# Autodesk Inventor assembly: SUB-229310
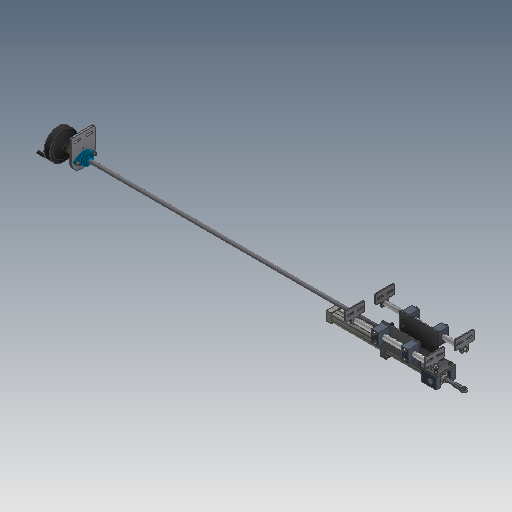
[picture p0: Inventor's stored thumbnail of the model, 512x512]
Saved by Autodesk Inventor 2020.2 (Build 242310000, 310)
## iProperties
Created: 2000-02
Part Number: SUB-229310
Document SubType Name: Assembly
Designer: sspink
Mass: 18139.2 g
Surface Area: 10168 cm^2
Volume: 3700.38 cm^3
Density: 4.90199 g/cm^3
Control State: 0
Checked Out: False
Master: False
Shininess: 0.0
Length Units: 11269
Angle Units: 11279
Time Units: 11290
Mass Units: 11283
Length Display Precision: 3
Angle Display Precision: 2
Compacted: True
Dimensions: 226,3x2253,1x261 mm
Mass: 18,139 kg
DocNumber: SUB-229310.iam
Folder: 01 - Themengebiete\Simplification\01 - Packaging machine\
VDS_Category: 3D Komponenten
Density: 0.0
Volumn: 0.0
Area: 0.0
PropertySet Name: Model Information
Author: sspink
Revision Number: -
Title: SUB-229310
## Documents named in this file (25)
- D:\07 - DEMODATEN\OTX 2019 - Dataset - UPDATE - Dez2019\Designs\07-Packing machine\SUB-229310.iam
- D:\07 - DEMODATEN\OTX 2019 - Dataset - UPDATE - Dez2019\Designs\07-Packing machine\Parts\ADSK-011610.ipt
- D:\07 - DEMODATEN\OTX 2019 - Dataset - UPDATE - Dez2019\Designs\07-Packing machine\Parts\ADSK-011611.ipt
- D:\07 - DEMODATEN\OTX 2019 - Dataset - UPDATE - Dez2019\Designs\07-Packing machine\Parts\ADSK-011577.ipt
- D:\07 - DEMODATEN\OTX 2019 - Dataset - UPDATE - Dez2019\Designs\07-Packing machine\Parts\ADSK-011333.ipt
- D:\07 - DEMODATEN\OTX 2019 - Dataset - UPDATE - Dez2019\Designs\07-Packing machine\Parts\ADSK-011576.ipt
- D:\07 - DEMODATEN\OTX 2019 - Dataset - UPDATE - Dez2019\Designs\07-Packing machine\500616.iam
- D:\07 - DEMODATEN\OTX 2019 - Dataset - UPDATE - Dez2019\Designs\07-Packing machine\500615.iam
- D:\07 - DEMODATEN\OTX 2019 - Dataset - UPDATE - Dez2019\Designs\07-Packing machine\A105157.iam
- D:\07 - DEMODATEN\OTX 2019 - Dataset - UPDATE - Dez2019\Designs\07-Packing machine\A081742.iam
- D:\07 - DEMODATEN\OTX 2019 - Dataset - UPDATE - Dez2019\Designs\07-Packing machine\Parts\ADSK-011614.ipt
- D:\07 - DEMODATEN\OTX 2019 - Dataset - UPDATE - Dez2019\Designs\07-Packing machine\Parts\ADSK-011714.ipt
- D:\07 - DEMODATEN\OTX 2019 - Dataset - UPDATE - Dez2019\Designs\07-Packing machine\Parts\ADSK-011309.ipt
- D:\07 - DEMODATEN\OTX 2019 - Dataset - UPDATE - Dez2019\Designs\07-Packing machine\Parts\ADSK-011768.ipt
- D:\07 - DEMODATEN\OTX 2019 - Dataset - UPDATE - Dez2019\Designs\07-Packing machine\Parts\ADSK-011615.ipt
- D:\07 - DEMODATEN\OTX 2019 - Dataset - UPDATE - Dez2019\Designs\07-Packing machine\Parts\ADSK-011725.ipt
- D:\07 - DEMODATEN\OTX 2019 - Dataset - UPDATE - Dez2019\Content Center Files\de-DE\DIN 125-1  B\DIN 125-1 - B 13.ipt
- D:\07 - DEMODATEN\OTX 2019 - Dataset - UPDATE - Dez2019\Content Center Files\de-DE\ISO 4762(2)\ISO 4762 - M12 x 25ISO.ipt
- D:\07 - DEMODATEN\OTX 2019 - Dataset - UPDATE - Dez2019\Content Center Files\de-DE\DIN 125-1  B\DIN 125-1 - B 8,4.ipt
- D:\07 - DEMODATEN\OTX 2019 - Dataset - UPDATE - Dez2019\Content Center Files\de-DE\ISO 4032(1)\ISO 4032 - M8DIN EN.ipt
- D:\07 - DEMODATEN\OTX 2019 - Dataset - UPDATE - Dez2019\Content Center Files\de-DE\ISO 4762(2)\ISO 4762 - M8 x 80ISO.ipt
- D:\07 - DEMODATEN\OTX 2019 - Dataset - UPDATE - Dez2019\Content Center Files\de-DE\ISO 4762(2)\ISO 4762 - M8 x 16ISO.ipt
- D:\07 - DEMODATEN\OTX 2019 - Dataset - UPDATE - Dez2019\Content Center Files\de-DE\ISO 4762(2)\ISO 4762 - M8 x 25ISO.ipt
- D:\07 - DEMODATEN\OTX 2019 - Dataset - UPDATE - Dez2019\Content Center Files\de-DE\DIN 125-1  B\DIN 125-1 - B 5,3.ipt
- D:\07 - DEMODATEN\OTX 2019 - Dataset - UPDATE - Dez2019\Content Center Files\de-DE\ISO 4762(2)\ISO 4762 - M5 x 8ISO.ipt
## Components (82 placed, 24 different names)
1. ADSK-011610:1 — Flush:1, Flush:2, Insert:1, Flush:3, Mate:1, Mate:2, Angle:2, Flush:7, Flush:8, Mate:16
2. ADSK-011610:2 — Flush:1, Flush:2, Insert:2, Angle:3, Flush:9, Flush:10
3. ADSK-011610:3 — Flush:7, Flush:8, Insert:10, Fluchtend:14
4. ADSK-011610:4 — Flush:9, Flush:10, Insert:11
5. ADSK-011611:1 — Insert:1, Insert:2, Mate:9, Mate:17
6. ADSK-011611:2 — Insert:10, Mate:12, Mate:13, Insert:11, Mate:18, Mate:19
7. 500616:1 [sub-assembly] — Angle:2, Angle:6, Mate:10, Mate:11, Flush:4, Flush:5, Flush:6, Mate:14, Mate:15, Flush:11, Insert:12, Insert:14, Flush:12, Passend:21, Passend:23, Passend:25, Passend:27, Passend:29, Passend:31, Passend:33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
8. ADSK-011333:1 — Passend:36, Passend:38, Passend:39, Passend:45
9. ADSK-011576:1 — Mate:9, Mate:10, Flush:6, Mate:17, Fluchtend:13
10. ADSK-011576:2 — Mate:11, Flush:4, Flush:5, Mate:16
11. 500615:1 [sub-assembly] — Insert:12, Passend:41, Passend:42
12. 500615:2 [sub-assembly] — Insert:14, Passend:40, Passend:44
13. ADSK-011577:1 — Einfügen:65, Einfügen:66, Passend:47, Passend:49
14. A105157:1 [sub-assembly] — Passend:42, Passend:43, Passend:44, Einfügen:52, Tangential:1
15. A081742:1 [sub-assembly] — Angle:6, Einfügen:52
16. ADSK-011309:1 — Insert:9, Passend:46
17. ADSK-011714:1 — Mate:3, Mate:6, Angle:4
18. ADSK-011768:1 — Mate:4, Mate:8, Angle:5
19. ADSK-011614:1 — Mate:3, Insert:9, Mate:4, Mate:5, Passend:45
20. ADSK-011615:1 — Mate:5, Angle:3, Mate:6, Angle:4, Mate:8, Angle:5, Fluchtend:14, Passend:46
21. ADSK-011576:3 — Mate:13, Mate:15, Flush:12, Mate:18
22. ADSK-011576:4 — Mate:12, Mate:14, Flush:11, Mate:19
23. ADSK-011725:1 — Passend:47, Tangential:1
24. DIN EN 24032 M8:9 — Passend:49
25. DIN 125-1 B B 5,3:1 — Passend:51, Passend:53
26. DIN 125-1 B B 5,3:2
27. ISO 4762 M5 x 8:1 — Passend:51
28. ISO 4762 M5 x 8:2 — Passend:53
29. ISO 4762 M8 x 16:1
30. ISO 4762 M8 x 16:2
31. DIN 125-1 B B 8,4:17
32. DIN 125-1 B B 8,4:18
33. DIN 125-1 B B 8,4:19
34. DIN 125-1 B B 8,4:20
35. ISO 4762 M8 x 25:1
36. ISO 4762 M8 x 25:2
37. ISO 4762 M8 x 25:3
38. ISO 4762 M8 x 25:4
39. DIN 125-1 B B 8,4:21
40. DIN 125-1 B B 8,4:22
41. ISO 4762 M8 x 25:5
42. ISO 4762 M8 x 25:6
43. DIN 125-1 B B 13:1
44. DIN 125-1 B B 13:2
45. DIN 125-1 B B 13:3
46. DIN 125-1 B B 13:4
47. ISO 4762 M12 x 25:1
48. ISO 4762 M12 x 25:2
49. ISO 4762 M12 x 25:3
50. ISO 4762 M12 x 25:4
51. DIN 125-1 B B 8,4:1
52. DIN 125-1 B B 8,4:2
53. DIN 125-1 B B 8,4:3
54. DIN 125-1 B B 8,4:4
55. DIN 125-1 B B 8,4:5
56. DIN 125-1 B B 8,4:6
57. DIN 125-1 B B 8,4:7
58. DIN 125-1 B B 8,4:8
59. DIN 125-1 B B 8,4:9 — Passend:21
60. DIN 125-1 B B 8,4:10 — Passend:23
61. DIN 125-1 B B 8,4:11 — Passend:25
62. DIN 125-1 B B 8,4:12 — Passend:27
63. DIN 125-1 B B 8,4:13 — Passend:29
64. DIN 125-1 B B 8,4:14 — Passend:31
65. DIN 125-1 B B 8,4:15 — Passend:33
66. DIN 125-1 B B 8,4:16 — Passend:35
67. DIN EN 24032 M8:1
68. DIN EN 24032 M8:2
69. DIN EN 24032 M8:3
70. DIN EN 24032 M8:4
71. DIN EN 24032 M8:5
72. DIN EN 24032 M8:6
73. DIN EN 24032 M8:7
74. DIN EN 24032 M8:8
75. ISO 4762 M8 x 80:1
76. ISO 4762 M8 x 80:2
77. ISO 4762 M8 x 80:3
78. ISO 4762 M8 x 80:4
79. ISO 4762 M8 x 80:5
80. ISO 4762 M8 x 80:6
81. ISO 4762 M8 x 80:7
82. ISO 4762 M8 x 80:8
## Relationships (70: Mate 40, Flush 14, Insert 10, Angle 5, Tangent 1)
- Flush:1: ADSK-011610:1 ↔ ADSK-011610:2
- Flush:2: ADSK-011610:1 ↔ ADSK-011610:2
- Insert:1: ADSK-011610:1 ↔ ADSK-011611:1
- Insert:2: ADSK-011610:2 ↔ ADSK-011611:1
- Flush:3: ADSK-011610:1
- Mate:1: ADSK-011610:1
- Mate:2: ADSK-011610:1
- Angle:2: ADSK-011610:1 ↔ 500616:1
- Mate:3: ADSK-011714:1 ↔ ADSK-011614:1
- Insert:9: ADSK-011309:1 ↔ ADSK-011614:1
- Mate:4: ADSK-011768:1 ↔ ADSK-011614:1
- Mate:5: ADSK-011614:1 ↔ ADSK-011615:1
- Angle:3: ADSK-011610:2 ↔ ADSK-011615:1
- Mate:6: ADSK-011714:1 ↔ ADSK-011615:1
- Angle:4: ADSK-011714:1 ↔ ADSK-011615:1
- Mate:8: ADSK-011768:1 ↔ ADSK-011615:1
- Angle:5: ADSK-011768:1 ↔ ADSK-011615:1
- Angle:6: 500616:1 ↔ A081742:1
- Mate:9: ADSK-011611:1 ↔ ADSK-011576:1
- Mate:10: 500616:1 ↔ ADSK-011576:1
- Mate:11: 500616:1 ↔ ADSK-011576:2
- Flush:4: 500616:1 ↔ ADSK-011576:2
- Flush:5: 500616:1 ↔ ADSK-011576:2
- Flush:6: 500616:1 ↔ ADSK-011576:1
- Flush:7: ADSK-011610:1 ↔ ADSK-011610:3
- Flush:8: ADSK-011610:1 ↔ ADSK-011610:3
- Flush:9: ADSK-011610:2 ↔ ADSK-011610:4
- Flush:10: ADSK-011610:2 ↔ ADSK-011610:4
- Insert:10: ADSK-011610:3 ↔ ADSK-011611:2
- Mate:12: ADSK-011611:2 ↔ ADSK-011576:4
- Mate:13: ADSK-011611:2 ↔ ADSK-011576:3
- Mate:14: 500616:1 ↔ ADSK-011576:4
- Mate:15: 500616:1 ↔ ADSK-011576:3
- Flush:11: 500616:1 ↔ ADSK-011576:4
- Insert:11: ADSK-011610:4 ↔ ADSK-011611:2
- Insert:12: 500616:1 ↔ 500615:1
- Insert:14: 500616:1 ↔ 500615:2
- Mate:16: ADSK-011610:1 ↔ ADSK-011576:2
- Flush:12: 500616:1 ↔ ADSK-011576:3
- Mate:17: ADSK-011611:1 ↔ ADSK-011576:1
- Mate:18: ADSK-011611:2 ↔ ADSK-011576:3
- Mate:19: ADSK-011611:2 ↔ ADSK-011576:4
- Passend:21 [Mate]: 500616:1 ↔ DIN 125-1 B B 8,4:9
- Passend:23 [Mate]: 500616:1 ↔ DIN 125-1 B B 8,4:10
- Passend:25 [Mate]: 500616:1 ↔ DIN 125-1 B B 8,4:11
- Passend:27 [Mate]: 500616:1 ↔ DIN 125-1 B B 8,4:12
- Passend:29 [Mate]: 500616:1 ↔ DIN 125-1 B B 8,4:13
- Passend:31 [Mate]: 500616:1 ↔ DIN 125-1 B B 8,4:14
- Passend:33 [Mate]: 500616:1 ↔ DIN 125-1 B B 8,4:15
- Passend:35 [Mate]: 500616:1 ↔ DIN 125-1 B B 8,4:16
- Passend:36 [Mate]: 500616:1 ↔ ADSK-011333:1
- Passend:38 [Mate]: 500616:1 ↔ ADSK-011333:1
- Fluchtend:13 [Flush]: 500616:1 ↔ ADSK-011576:1
- Passend:39 [Mate]: 500616:1 ↔ ADSK-011333:1
- Passend:40 [Mate]: 500616:1 ↔ 500615:2
- Passend:41 [Mate]: 500616:1 ↔ 500615:1
- Passend:42 [Mate]: 500615:1 ↔ A105157:1
- Passend:43 [Mate]: 500616:1 ↔ A105157:1
- Passend:44 [Mate]: 500615:2 ↔ A105157:1
- Einfügen:52 [Insert]: A105157:1 ↔ A081742:1
- Passend:45 [Mate]: ADSK-011333:1 ↔ ADSK-011614:1
- Fluchtend:14 [Flush]: ADSK-011610:3 ↔ ADSK-011615:1
- Passend:46 [Mate]: ADSK-011309:1 ↔ ADSK-011615:1
- Einfügen:65 [Insert]: 500616:1 ↔ ADSK-011577:1
- Einfügen:66 [Insert]: 500616:1 ↔ ADSK-011577:1
- Passend:47 [Mate]: ADSK-011577:1 ↔ ADSK-011725:1
- Tangential:1: A105157:1 ↔ ADSK-011725:1
- Passend:49 [Mate]: ADSK-011577:1 ↔ DIN EN 24032 M8:9
- Passend:51 [Mate]: DIN 125-1 B B 5,3:1 ↔ ISO 4762 M5 x 8:1
- Passend:53 [Mate]: DIN 125-1 B B 5,3:1 ↔ ISO 4762 M5 x 8:2
